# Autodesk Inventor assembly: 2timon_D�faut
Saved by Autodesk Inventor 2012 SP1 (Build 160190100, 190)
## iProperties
Created: 2011-01
Part Number: 2timon_D�faut
Document SubType Name: Assembly
Designer: eric
Mass: 68.6923 g
Surface Area: 1295.09 cm^2
Volume: 68.6923 cm^3
Density: 1 g/cm^3
Author: eric
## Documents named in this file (12)
- D:\Cours\Inventor salle SI\chariot_de_golf_2008\chariot_de_golf_trolem\2timon_Defaut.iam
- D:\Cours\Inventor salle SI\chariot_de_golf_2008\chariot_de_golf_trolem\bossage3_Defaut.ipt
- D:\Cours\Inventor salle SI\chariot_de_golf_2008\chariot_de_golf_trolem\bossage1_Defaut.ipt
- D:\Cours\Inventor salle SI\chariot_de_golf_2008\chariot_de_golf_trolem\bead31_Defaut.ipt
- D:\Cours\Inventor salle SI\chariot_de_golf_2008\chariot_de_golf_trolem\bossage2_Defaut.ipt
- D:\Cours\Inventor salle SI\chariot_de_golf_2008\chariot_de_golf_trolem\bead36_Defaut.ipt
- D:\Cours\Inventor salle SI\chariot_de_golf_2008\chariot_de_golf_trolem\2timon_tube_Defaut.ipt
- D:\Cours\Inventor salle SI\chariot_de_golf_2008\chariot_de_golf_trolem\bead35_Defaut.ipt
- D:\Cours\Inventor salle SI\chariot_de_golf_2008\chariot_de_golf_trolem\bead33_Defaut.ipt
- D:\Cours\Inventor salle SI\chariot_de_golf_2008\chariot_de_golf_trolem\bead34_Defaut.ipt
- D:\Cours\Inventor salle SI\chariot_de_golf_2008\chariot_de_golf_trolem\48Axe_8_55_Defaut.ipt
- D:\Cours\Inventor salle SI\chariot_de_golf_2008\chariot_de_golf_trolem\bead30_Defaut.ipt
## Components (11 placed, 11 different names)
1. bossage3_Defaut:1
2. bossage1_Defaut:1
3. bead31_Defaut:1
4. bossage2_Defaut:1
5. bead36_Defaut:1
6. 2timon_tube_Defaut:1
7. bead35_Defaut:1
8. bead33_Defaut:1
9. bead34_Defaut:1
10. 48Axe_8_55_Defaut:1
11. bead30_Defaut:1
